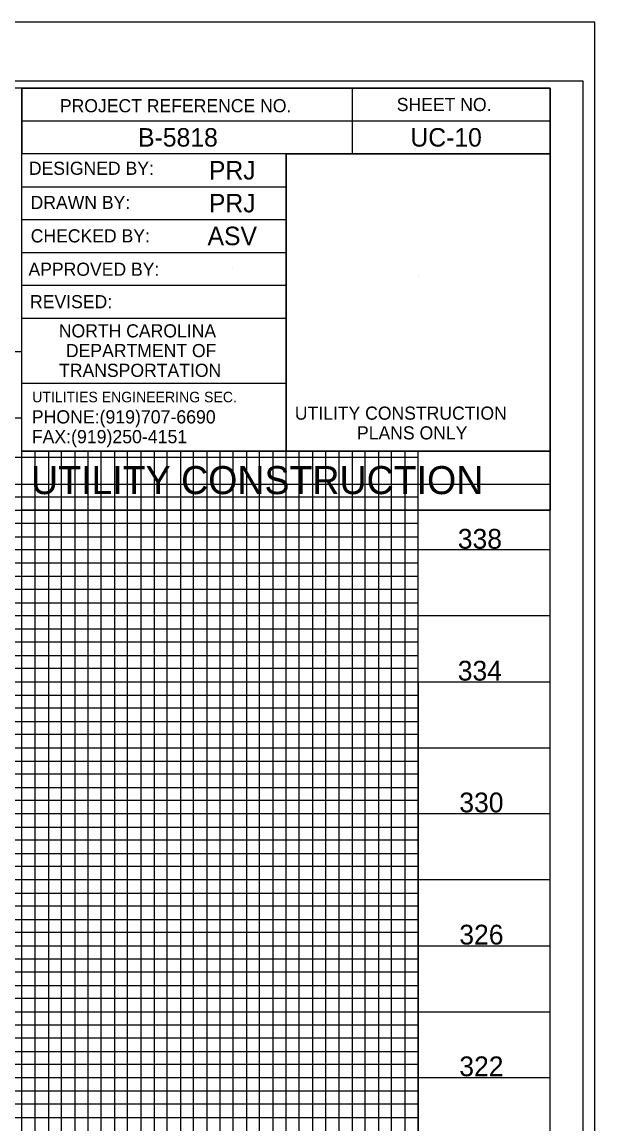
# Model space of a CAD drawing. Extents: x 3814791 to 3815465, y 1224203 to 1224643.
# Drawn here: x 3815378.1 to 3815464.9, y 1224476.2 to 1224643.2 of the extents above; entities that cross this region are included whole.
import ezdxf

# ---------------------------------------------------------------- set-up
doc = ezdxf.new("R2010")
doc.units = 0
for name, color, linetype in [('Exist Roads EOP', 7, 'Continuous'), ('General Text and Text Box and Leader Line', 7, 'Continuous'), ('Old_Level_35', 7, 'Continuous'), ('Pattern 49', 7, 'Continuous'), ('Prop 8 In Water Line (St)', 7, 'Continuous'), ('Scratch_Level_1', 7, 'Continuous'), ('Scratch_Level_9', 7, 'Continuous'), ('UC Full Profile Sheet 34 CELL', 7, 'Continuous')]:
    doc.layers.add(name, color=color, linetype=linetype)

msp = doc.modelspace()

# ---------------------------------------------------------------- linework, layer by layer
at = {"layer": 'Exist Roads EOP'}
for p, q in [((3815378.11, 1224623.19), (3815378.13, 1224633.21)), ((3815378.13, 1224633.21), (3815458.11, 1224633.21)), ((3815378.13, 1224623.25), (3815378.13, 1224633.21)), ((3815428.14, 1224633.19), (3815428.14, 1224623.23)), ((3815458.11, 1224633.21), (3815458.11, 1224623.25)), ((3815378.13, 1224628.21), (3815458.13, 1224628.21)), ((3815403.13, 1224625.73), (3815403.13, 1224625.73)), ((3815443.12, 1224625.73), (3815443.12, 1224625.73)), ((3815458.11, 1224623.25), (3815378.13, 1224623.25)), ((3815409.94, 1224620.74), (3815409.94, 1224620.74)), ((3815378.13, 1224618.25), (3815418.14, 1224618.25)), ((3815409.94, 1224615.76), (3815409.94, 1224615.76)), ((3815378.13, 1224613.27), (3815418.14, 1224613.27)), ((3815409.94, 1224610.79), (3815409.94, 1224610.79)), ((3815378.13, 1224608.29), (3815418.14, 1224608.29)), ((3815409.94, 1224605.81), (3815409.94, 1224605.81)), ((3815438.13, 1224604.75), (3815438.13, 1224604.75)), ((3815378.13, 1224603.32), (3815418.14, 1224603.32)), ((3815378.13, 1224598.33), (3815418.14, 1224598.33)), ((3815378.13, 1224588.46), (3815418.14, 1224588.46)), ((3815438.11, 1224561.21), (3814878.11, 1224561.21)), ((3814878.11, 1224559.21), (3815438.11, 1224559.21)), ((3815438.11, 1224551.21), (3814878.11, 1224551.21))]:
    msp.add_line(p, q, dxfattribs=at)
for points in [[(3815458.11, 1224633.21), (3814858.11, 1224633.21), (3814858.11, 1224213.21), (3815458.11, 1224213.21)], [(3814878.11, 1224633.21), (3814878.11, 1224223.21), (3815438.11, 1224223.21), (3815438.11, 1224578.19), (3815378.11, 1224578.19), (3815378.11, 1224633.21)], [(3815418.14, 1224623.25), (3815458.11, 1224623.25), (3815458.11, 1224578.19), (3815418.14, 1224578.19)]]:
    msp.add_lwpolyline(points, close=True, dxfattribs=at)
for points in [[(3815378.11, 1224223.21), (3815378.11, 1224633.21), (3815388.63, 1224633.21)], [(3815418.14, 1224623.25), (3815418.14, 1224578.19), (3815378.11, 1224578.19), (3815378.11, 1224633.21), (3815418.14, 1224633.21), (3815418.14, 1224633.15)], [(3815378.09, 1224593.21), (3814858.11, 1224593.21), (3814858.11, 1224573.19), (3815458.11, 1224573.19)], [(3815458.11, 1224563.21), (3814858.11, 1224563.21), (3814858.11, 1224583.21), (3815378.09, 1224583.21)], [(3815380.11, 1224223.21), (3815380.11, 1224578.19)], [(3815382.11, 1224578.19), (3815382.11, 1224223.21), (3815384.11, 1224223.21), (3815384.11, 1224578.19)], [(3815386.11, 1224578.19), (3815386.11, 1224223.21), (3815390.11, 1224223.21), (3815390.11, 1224578.19)], [(3815388.11, 1224578.19), (3815388.11, 1224223.21), (3815408.11, 1224223.21), (3815408.11, 1224578.19)], [(3815392.11, 1224578.19), (3815392.11, 1224223.21), (3815394.11, 1224223.21), (3815394.11, 1224578.19)], [(3815396.11, 1224578.19), (3815396.11, 1224223.21), (3815400.11, 1224223.21), (3815400.11, 1224578.19)], [(3815398.11, 1224578.19), (3815398.11, 1224223.21), (3815418.11, 1224223.21), (3815418.11, 1224578.19)], [(3815402.11, 1224578.19), (3815402.11, 1224223.21), (3815404.11, 1224223.21), (3815404.11, 1224578.19)], [(3815406.11, 1224578.19), (3815406.11, 1224223.21), (3815410.11, 1224223.21), (3815410.11, 1224578.19)], [(3815412.11, 1224578.19), (3815412.11, 1224223.21)], [(3815412.11, 1224223.21), (3815414.11, 1224223.21), (3815414.11, 1224578.19)], [(3815416.11, 1224578.19), (3815416.11, 1224223.21), (3815420.11, 1224223.21), (3815420.11, 1224578.19)], [(3815422.11, 1224578.19), (3815422.11, 1224223.21)], [(3815424.11, 1224578.19), (3815424.11, 1224223.21)], [(3815426.11, 1224578.19), (3815426.11, 1224223.21), (3815430.11, 1224223.21), (3815430.11, 1224578.19)], [(3815428.11, 1224578.19), (3815428.11, 1224223.21)], [(3815432.11, 1224578.19), (3815432.11, 1224223.21), (3815434.11, 1224223.21), (3815434.11, 1224578.19)], [(3815436.11, 1224578.19), (3815436.11, 1224223.21), (3815440.11, 1224223.21)], [(3815438.11, 1224577.21), (3814878.11, 1224577.21), (3814878.11, 1224577.21), (3814878.11, 1224569.21), (3815458.11, 1224569.21)], [(3815438.11, 1224571.21), (3814878.11, 1224571.21)], [(3815438.11, 1224567.21), (3814878.11, 1224567.21), (3814878.11, 1224565.21), (3815438.11, 1224565.21)], [(3815438.11, 1224557.21), (3814878.11, 1224557.21), (3814878.11, 1224555.21), (3815438.11, 1224555.21)], [(3815458.11, 1224553.21), (3814858.11, 1224553.21), (3814858.11, 1224533.21), (3815458.11, 1224533.21)], [(3815438.11, 1224549.21), (3814878.11, 1224549.21), (3814878.11, 1224547.21), (3815438.11, 1224547.21)], [(3815438.11, 1224545.21), (3814878.11, 1224545.21)], [(3815458.11, 1224523.21), (3814858.11, 1224523.21), (3814858.11, 1224543.21), (3815458.11, 1224543.21)], [(3815438.11, 1224543.21), (3815438.11, 1224223.21)], [(3814878.11, 1224541.21), (3815438.11, 1224541.21)], [(3815438.11, 1224539.21), (3814878.11, 1224539.21), (3814878.11, 1224537.21), (3815438.11, 1224537.21)], [(3815438.11, 1224535.21), (3814878.11, 1224535.21), (3814878.11, 1224531.21), (3815438.11, 1224531.21)], [(3815438.11, 1224529.21), (3814878.11, 1224529.21), (3814878.11, 1224527.21), (3815438.11, 1224527.21)], [(3815438.11, 1224525.21), (3814878.11, 1224525.21), (3814878.11, 1224521.21), (3815438.11, 1224521.21)], [(3815438.11, 1224519.21), (3814878.11, 1224519.21), (3814878.11, 1224517.21), (3815438.11, 1224517.21)], [(3815438.11, 1224515.21), (3814878.11, 1224515.21), (3814878.11, 1224511.21), (3815438.11, 1224511.21)], [(3815458.11, 1224513.21), (3814858.11, 1224513.21), (3814858.11, 1224493.21), (3815458.11, 1224493.21)], [(3815438.11, 1224509.21), (3814878.11, 1224509.21), (3814878.11, 1224507.21), (3815438.11, 1224507.21)], [(3815438.11, 1224505.21), (3814878.11, 1224505.21), (3814878.11, 1224501.21), (3815438.11, 1224501.21)], [(3815458.11, 1224483.21), (3814858.11, 1224483.21), (3814858.11, 1224503.21), (3815458.11, 1224503.21)], [(3815438.11, 1224499.21), (3814878.11, 1224499.21), (3814878.11, 1224497.21), (3815438.11, 1224497.21)], [(3815438.11, 1224495.21), (3814878.11, 1224495.21), (3814878.11, 1224491.21), (3815438.11, 1224491.21)], [(3815438.11, 1224489.21), (3814878.11, 1224489.21), (3814878.11, 1224487.21), (3815438.11, 1224487.21)], [(3815438.11, 1224485.21), (3814878.11, 1224485.21), (3814878.11, 1224481.21), (3815438.11, 1224481.21)], [(3815438.11, 1224479.21), (3814878.11, 1224479.21), (3814878.11, 1224477.21), (3815438.11, 1224477.21)]]:
    msp.add_lwpolyline(points, dxfattribs=at)
at = {"layer": 'Old_Level_35'}
msp.add_lwpolyline([(3815378.11, 1224578.19), (3815458.11, 1224578.19), (3815458.11, 1224569.21), (3815378.11, 1224569.21)], close=True, dxfattribs=at)
at = {"layer": 'Pattern 49'}
msp.add_lwpolyline([(3815463.11, 1224634.23), (3814796.51, 1224634.23), (3814796.51, 1224212.19), (3815463.11, 1224212.19)], close=True, dxfattribs=at)
at = {"layer": 'Scratch_Level_1'}
msp.add_lwpolyline([(3815464.91, 1224643.21), (3814791.31, 1224643.21), (3814791.31, 1224203.21), (3815464.91, 1224203.21)], close=True, dxfattribs=at)
at = {"layer": 'UC Full Profile Sheet 34 CELL'}
msp.add_lwpolyline([(3815378.11, 1224578.19), (3815458.11, 1224578.19), (3815458.11, 1224569.21), (3815416.02, 1224569.21), (3815402.09, 1224569.21), (3815378.11, 1224569.21)], close=True, dxfattribs=at)

# ---------------------------------------------------------------- texts
at = {"layer": 'Exist Roads EOP'}
for s, height, p in [('PROJECT REFERENCE NO.', 1.9916, (3815383.85, 1224629.53)), ('SHEET NO.', 1.992, (3815434.88, 1224629.71)), ('DESIGNED BY:', 1.9916, (3815379.15, 1224620.05)), ('DRAWN BY:', 1.992, (3815379.41, 1224614.87)), ('CHECKED BY:', 1.9916, (3815379.43, 1224609.81)), ('APPROVED BY:', 1.9916, (3815379.09, 1224604.75)), ('REVISED:', 1.992, (3815379.33, 1224599.83)), ('NORTH CAROLINA', 1.9916, (3815383.69, 1224595.41)), ('DEPARTMENT OF', 1.9916, (3815384.77, 1224592.42)), ('TRANSPORTATION', 1.9916, (3815383.73, 1224589.43)), ('UTILITIES ENGINEERING SEC.', 1.5933, (3815379.65, 1224585.58)), ('UTILITY CONSTRUCTION', 1.9916, (3815419.44, 1224582.94)), ('PLANS ONLY', 1.992, (3815428.86, 1224579.95))]:
    msp.add_text(s, height=height, rotation=360, dxfattribs=at).set_placement(p)
at = {"layer": 'General Text and Text Box and Leader Line'}
for s, p in [('338', (3815444.13, 1224563.39)), ('334', (3815444.12, 1224543.4)), ('330', (3815444.36, 1224523.43)), ('326', (3815444.36, 1224503.4)), ('322', (3815444.36, 1224483.44))]:
    msp.add_text(s, height=3, dxfattribs=at).set_placement(p)
at = {"layer": 'Old_Level_35'}
msp.add_text('UTILITY CONSTRUCTION', height=4.25, rotation=360, dxfattribs=at).set_placement((3815379.48, 1224571.66))
at = {"layer": 'Prop 8 In Water Line (St)'}
for s, p in [('B-5818', (3815395.7, 1224624.33)), ('UC-10', (3815436.95, 1224624.33)), ('PRJ', (3815406.43, 1224619.34)), ('PRJ', (3815406.43, 1224614.36)), ('ASV', (3815406.22, 1224609.39))]:
    msp.add_text(s, height=2.8, dxfattribs=at).set_placement(p)
at = {"layer": 'Scratch_Level_9'}
for s, p in [('PHONE:(919)707-6690', (3815379.59, 1224582.37)), ('FAX:(919)250-4151', (3815379.59, 1224579.37))]:
    msp.add_text(s, height=2.0046, rotation=360, dxfattribs=at).set_placement(p)

doc.saveas('drawing.dxf')
